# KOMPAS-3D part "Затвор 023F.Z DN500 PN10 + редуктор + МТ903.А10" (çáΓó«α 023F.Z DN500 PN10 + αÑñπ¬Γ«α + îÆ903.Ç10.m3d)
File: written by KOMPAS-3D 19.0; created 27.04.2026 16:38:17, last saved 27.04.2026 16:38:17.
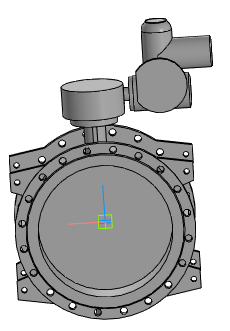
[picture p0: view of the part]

Document properties: Полное имя файла: ..\..\Затвор 023F.Z DN400-DN1600 + редуктор + МТ903\Затвор 023F.Z DN500 PN10 + редуктор + МТ903.А10.a3d

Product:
- Part/product: Затвор 023F.Z DN500 PN10 + редуктор + МТ903.А10
    Масса: 335.495

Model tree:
1. Операция без истории:1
